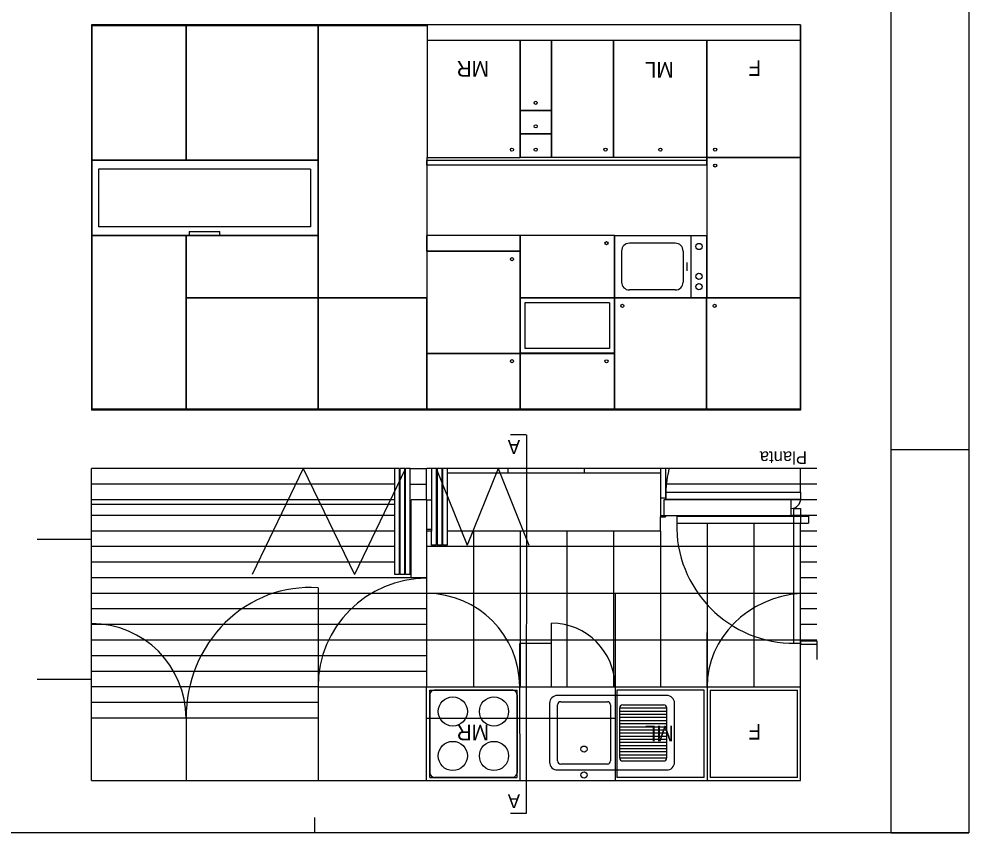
# Model space of a CAD drawing. Extents: x 1323.1 to 1334.7, y -308.5 to -300.1.
# Drawn here: x 1328.58 to 1334.67, y -308.54 to -303.32 of the extents above; entities that cross this region are included whole.
import ezdxf

# ---------------------------------------------------------------- set-up
doc = ezdxf.new("R2010")
doc.units = 0
for name, color, linetype in [('Level 1', 7, 'Continuous'), ('Level 10', 7, 'Continuous'), ('Level 11', 7, 'Continuous'), ('Level 13', 7, 'Continuous'), ('Level 2', 7, 'Continuous'), ('Level 3', 7, 'Continuous'), ('Level 31', 7, 'Continuous'), ('Level 37', 7, 'Continuous'), ('Level 4', 7, 'Continuous'), ('Level 59', 7, 'Continuous'), ('Level 60', 7, 'Continuous'), ('Level 62', 7, 'Continuous')]:
    doc.layers.add(name, color=color, linetype=linetype)

msp = doc.modelspace()

# ---------------------------------------------------------------- linework, layer by layer
at = {"layer": 'Level 1'}
for p, q in [((1333.5921, -303.3551), (1329.0421, -303.3551)), ((1329.0421, -303.3551), (1329.0421, -305.8251)), ((1333.5921, -303.3551), (1333.5921, -305.8251)), ((1333.5921, -305.8251), (1329.0421, -305.8251)), ((1329.0421, -306.6532), (1329.0421, -306.2007)), ((1331.1921, -306.4007), (1331.1921, -306.2007)), ((1331.2241, -306.2007), (1331.1935, -306.2007)), ((1331.2241, -306.2007), (1331.2241, -306.6007)), ((1332.6921, -306.2007), (1332.6921, -306.5107)), ((1332.7241, -306.2007), (1332.6921, -306.2007)), ((1332.7241, -306.2007), (1332.7241, -306.4007)), ((1331.0921, -306.9007), (1331.0921, -306.4007)), ((1331.1921, -306.4007), (1331.0921, -306.4007)), ((1331.1921, -306.4007), (1331.1921, -306.9007)), ((1331.1921, -306.4007), (1331.2241, -306.4007)), ((1332.7241, -306.3907), (1332.6921, -306.3907)), ((1332.6921, -306.4007), (1332.6921, -306.5007)), ((1333.5321, -306.4007), (1332.7141, -306.4007)), ((1332.7141, -306.4007), (1332.7141, -306.5007)), ((1333.5321, -306.5007), (1333.5321, -306.4007)), ((1333.5321, -306.5007), (1333.5321, -306.4007)), ((1332.6921, -306.5007), (1333.5321, -306.5007)), ((1332.6921, -306.5107), (1332.7241, -306.5107)), ((1332.7141, -306.5007), (1333.5321, -306.5007)), ((1332.7241, -306.5007), (1332.7241, -306.5107)), ((1331.2241, -306.5907), (1331.1921, -306.5907)), ((1328.6921, -306.6532), (1329.0421, -306.6532)), ((1331.2241, -306.6007), (1331.1921, -306.6007)), ((1331.1921, -306.9007), (1331.0921, -306.9007)), ((1333.5921, -307.3257), (1333.6971, -307.3257)), ((1333.5921, -308.2007), (1333.5921, -307.3257)), ((1333.5921, -308.2007), (1333.5921, -307.3257)), ((1333.6971, -307.3257), (1333.6971, -307.4257)), ((1329.0421, -307.5532), (1328.6921, -307.5532)), ((1329.0421, -308.2007), (1329.0421, -307.5507)), ((1329.0421, -308.2007), (1329.0421, -307.5532)), ((1329.0421, -308.2007), (1333.5921, -308.2007)), ((1329.0421, -308.2007), (1330.7921, -308.2007)), ((1330.8921, -308.2007), (1333.5921, -308.2007))]:
    msp.add_line(p, q, dxfattribs=at)
at = {"layer": 'Level 10'}
for p, q in [((1330.9871, -306.2007), (1329.0421, -306.2007)), ((1331.0871, -306.2007), (1331.1935, -306.2007)), ((1333.6971, -306.2007), (1332.7241, -306.2007)), ((1330.9871, -306.3007), (1329.0421, -306.3007)), ((1331.0871, -306.3007), (1331.1921, -306.3007)), ((1333.6971, -306.3007), (1332.7241, -306.3007)), ((1330.9871, -306.4007), (1329.0421, -306.4007)), ((1333.6971, -306.4007), (1333.5321, -306.4007)), ((1330.9871, -306.5007), (1329.0421, -306.5007)), ((1333.6971, -306.5007), (1333.5321, -306.5007)), ((1332.9921, -306.5507), (1332.9921, -307.6007)), ((1333.2921, -306.5507), (1333.2921, -307.6007)), ((1333.5921, -307.3057), (1333.5921, -306.5507)), ((1330.9871, -306.6007), (1329.0421, -306.6007)), ((1331.4921, -306.6007), (1331.4921, -307.5977)), ((1331.7921, -306.6007), (1331.7921, -307.6007)), ((1332.0921, -306.6007), (1332.0921, -307.6007)), ((1332.3921, -306.6007), (1332.3921, -307.6007)), ((1332.6921, -306.6007), (1332.6921, -307.6007)), ((1333.6971, -306.6007), (1333.5921, -306.6007)), ((1330.9871, -306.7007), (1329.0421, -306.7007)), ((1333.5921, -306.7007), (1331.1921, -306.7007)), ((1333.6971, -306.7007), (1333.5921, -306.7007)), ((1330.9871, -306.8007), (1329.0421, -306.8007)), ((1333.6971, -306.8007), (1333.5921, -306.8007)), ((1331.0921, -306.9007), (1329.0421, -306.9007)), ((1331.1921, -306.9007), (1331.1921, -307.5977)), ((1333.6971, -306.9007), (1333.5921, -306.9007)), ((1333.5921, -307.0007), (1329.0421, -307.0007)), ((1333.6971, -307.0007), (1333.5921, -307.0007)), ((1331.1921, -307.1007), (1329.0421, -307.1007)), ((1333.6971, -307.1007), (1333.5921, -307.1007)), ((1331.1921, -307.2007), (1329.0421, -307.2007)), ((1333.6971, -307.2007), (1333.5921, -307.2007)), ((1333.5921, -307.3007), (1329.0421, -307.3007)), ((1333.6971, -307.3007), (1333.5921, -307.3007)), ((1331.1921, -307.4007), (1329.0421, -307.4007)), ((1331.1921, -307.5007), (1329.0421, -307.5007)), ((1330.4951, -307.6007), (1329.0421, -307.6007)), ((1330.4951, -307.7007), (1329.0421, -307.7007))]:
    msp.add_line(p, q, dxfattribs=at)
at = {"layer": 'Level 11'}
for p, q in [((1331.7901, -304.7051), (1331.1941, -304.7051)), ((1331.1941, -304.8051), (1331.1941, -304.7051)), ((1331.7901, -304.7051), (1331.7901, -304.8051)), ((1332.3981, -304.7051), (1332.3981, -305.1051)), ((1332.3981, -304.7051), (1332.9881, -304.7051)), ((1332.8881, -304.7051), (1332.8881, -305.1051)), ((1332.9881, -304.7051), (1332.9881, -305.1051)), ((1332.7881, -304.7551), (1332.4931, -304.7551)), ((1331.7901, -304.8051), (1331.1941, -304.8051)), ((1332.4431, -304.8051), (1332.4431, -305.0051)), ((1332.8381, -304.8051), (1332.8381, -305.0051)), ((1332.8626, -304.8784), (1332.8626, -304.9318)), ((1332.7881, -305.0551), (1332.4931, -305.0551)), ((1332.9881, -305.1051), (1332.3981, -305.1051)), ((1331.7421, -307.6206), (1331.2421, -307.6206)), ((1333.0121, -307.6207), (1333.5721, -307.6207)), ((1333.0121, -307.6207), (1333.0121, -308.1807)), ((1333.5721, -308.1807), (1333.5721, -307.6207)), ((1331.2121, -307.6506), (1331.2121, -308.1506)), ((1331.7721, -307.6506), (1331.7721, -308.1506)), ((1332.0525, -307.6956), (1332.3525, -307.6956)), ((1332.0325, -308.0756), (1332.0325, -307.7156)), ((1332.3725, -307.7156), (1332.3725, -308.0756)), ((1332.431, -308.0556), (1332.431, -307.7356)), ((1332.431, -307.7356), (1332.7325, -307.7356)), ((1332.431, -307.7556), (1332.7325, -307.7556)), ((1332.4509, -307.7156), (1332.7125, -307.7156)), ((1332.7325, -308.0556), (1332.7325, -307.7356)), ((1332.431, -307.7756), (1332.7325, -307.7756)), ((1332.431, -307.7956), (1332.7325, -307.7956)), ((1332.431, -307.8156), (1332.7325, -307.8156)), ((1332.431, -307.8356), (1332.7325, -307.8356)), ((1332.431, -307.8556), (1332.7325, -307.8556)), ((1332.431, -307.8756), (1332.7325, -307.8756)), ((1332.431, -307.8956), (1332.7325, -307.8956)), ((1332.431, -307.9156), (1332.7325, -307.9156)), ((1332.431, -307.9356), (1332.7325, -307.9356)), ((1332.431, -307.9556), (1332.7325, -307.9556)), ((1332.431, -307.9756), (1332.7325, -307.9756)), ((1332.431, -307.9956), (1332.7325, -307.9956)), ((1332.431, -308.0156), (1332.7325, -308.0156)), ((1332.431, -308.0356), (1332.7325, -308.0356)), ((1332.431, -308.0556), (1332.7325, -308.0556)), ((1332.3525, -308.0956), (1332.0525, -308.0956)), ((1332.4509, -308.0756), (1332.7125, -308.0756)), ((1331.7421, -308.1806), (1331.2421, -308.1806)), ((1333.5721, -308.1807), (1333.0121, -308.1807))]:
    msp.add_line(p, q, dxfattribs=at)
for points in [[(1332.7328, -307.655), (1332.0314, -307.655)], [(1331.9814, -307.705), (1331.9814, -308.0834)], [(1332.7828, -308.0834), (1332.7828, -307.705)], [(1332.0314, -308.1334), (1332.7328, -308.1334)]]:
    msp.add_lwpolyline(points, dxfattribs=at)
for centre, radius in [((1332.9399, -304.7762), 0.02), ((1332.9399, -304.9668), 0.02), ((1332.9399, -305.0333), 0.02), ((1331.36, -307.758), 0.0936), ((1331.6242, -307.758), 0.0936), ((1331.36, -308.0432), 0.0936), ((1331.6242, -308.0432), 0.0936), ((1332.2025, -307.9996), 0.0199), ((1332.2025, -308.1655), 0.0199)]:
    msp.add_circle(centre, radius, dxfattribs=at)
for centre, radius, start, end in [((1332.4931, -304.8051), 0.05, 90, 180), ((1332.7881, -304.8051), 0.05, 0, 90), ((1332.4931, -305.0051), 0.05, 180, 270), ((1332.7881, -305.0051), 0.05, 270, 0), ((1331.2421, -307.6506), 0.03, 89.99998, 179.99995), ((1331.7421, -307.6506), 0.03, 359.9999, 89.99991), ((1332.0313, -307.705), 0.05, 90, 180), ((1332.0525, -307.7156), 0.02, 90, 180), ((1332.3525, -307.7156), 0.02, 0, 90), ((1332.7328, -307.705), 0.05, 0, 90), ((1332.4509, -307.7356), 0.02, 90, 180), ((1332.7125, -307.7356), 0.02, 0, 90), ((1332.4509, -308.0556), 0.02, 180, 270), ((1332.7125, -308.0556), 0.02, 270, 0), ((1332.0313, -308.0834), 0.05, 180, 270), ((1332.0525, -308.0756), 0.02, 180, 270), ((1332.3525, -308.0756), 0.02, 270, 0), ((1332.7328, -308.0834), 0.05, 270, 0), ((1331.2421, -308.1506), 0.03, 180.00001, 269.99979), ((1331.7421, -308.1506), 0.03, 269.9998, 0.00015)]:
    msp.add_arc(centre, radius, start, end, dxfattribs=at)
at = {"layer": 'Level 13'}
for p, q in [((1329.5141, -303.3601), (1329.0421, -303.3601)), ((1329.0441, -303.3601), (1329.0441, -304.2231)), ((1329.0441, -303.3601), (1329.0441, -304.7051)), ((1331.1921, -303.3601), (1329.5161, -303.3601)), ((1329.6461, -303.3601), (1329.6461, -304.2231)), ((1329.6481, -303.3601), (1329.6481, -304.2231)), ((1330.4941, -303.3551), (1330.4941, -304.2231)), ((1330.4961, -303.3551), (1330.4961, -305.1051)), ((1331.1948, -303.3551), (1331.1948, -304.2051)), ((1333.5901, -303.3551), (1333.5901, -305.1047)), ((1332.9941, -303.4551), (1331.1948, -303.4551)), ((1331.7898, -303.4551), (1331.1948, -303.4551)), ((1331.1948, -303.4551), (1331.1948, -304.2031)), ((1331.7901, -303.4551), (1331.7901, -304.2051)), ((1331.7921, -303.4551), (1331.7921, -303.9031)), ((1331.9921, -303.4551), (1331.9921, -303.9031)), ((1331.9941, -303.4551), (1331.9941, -304.2051)), ((1332.3901, -303.4551), (1332.3901, -304.2051)), ((1332.3921, -303.4551), (1332.3921, -304.2051)), ((1332.9881, -303.4551), (1332.9881, -304.2251)), ((1332.9901, -303.4551), (1332.9901, -305.1047)), ((1333.5901, -303.4551), (1332.9941, -303.4551)), ((1333.5901, -303.4551), (1333.5901, -305.8201)), ((1331.9921, -303.9031), (1331.7921, -303.9031)), ((1331.9921, -303.9051), (1331.7921, -303.9051)), ((1331.7921, -303.9051), (1331.7921, -304.0531)), ((1331.9921, -303.9051), (1331.9921, -304.0531)), ((1331.9921, -304.0531), (1331.7921, -304.0531)), ((1331.9921, -304.0551), (1331.7921, -304.0551)), ((1331.7921, -304.0551), (1331.7921, -304.2051)), ((1331.9921, -304.0551), (1331.9921, -304.2051)), ((1331.1941, -304.2051), (1331.7923, -304.2051)), ((1331.1941, -304.2051), (1331.1941, -305.8201)), ((1331.9921, -304.2051), (1331.7921, -304.2051)), ((1332.9881, -304.2051), (1331.9921, -304.2051)), ((1333.5901, -304.2051), (1332.9901, -304.2051)), ((1333.5901, -304.2071), (1332.9901, -304.2071)), ((1329.6461, -304.2231), (1329.0441, -304.2231)), ((1330.4941, -304.2251), (1329.0441, -304.2251)), ((1330.4459, -304.2801), (1329.0871, -304.2801)), ((1329.0871, -304.2801), (1329.0871, -304.6501)), ((1330.4941, -304.2231), (1329.6481, -304.2231)), ((1330.4459, -304.2801), (1330.4459, -304.6501)), ((1330.4941, -304.2251), (1330.4941, -304.7051)), ((1330.4941, -304.7051), (1329.0441, -304.7051)), ((1329.0441, -304.7071), (1329.0441, -305.8201)), ((1329.6461, -304.7071), (1329.0441, -304.7071)), ((1330.4459, -304.6501), (1329.0871, -304.6501)), ((1329.6461, -304.7071), (1329.6461, -305.8201)), ((1329.6481, -304.7051), (1329.8431, -304.7051)), ((1330.4941, -304.7071), (1329.6481, -304.7071)), ((1329.6481, -304.7071), (1329.6481, -305.1051)), ((1329.669, -304.6801), (1329.864, -304.6801)), ((1329.669, -304.6801), (1329.669, -304.7051)), ((1329.864, -304.7051), (1329.864, -304.6801)), ((1330.4941, -304.7071), (1330.4941, -305.1051)), ((1332.3981, -304.7051), (1331.7901, -304.7051)), ((1331.7921, -304.7051), (1331.7921, -305.1051)), ((1332.3961, -304.7051), (1332.3961, -305.1051)), ((1331.1941, -304.8071), (1331.7901, -304.8071)), ((1331.7901, -304.8071), (1331.7901, -305.4601)), ((1330.4941, -305.1051), (1329.6481, -305.1051)), ((1329.6481, -305.1071), (1329.6481, -305.8201)), ((1330.1401, -305.1071), (1329.6481, -305.1071)), ((1330.4941, -305.1071), (1330.1421, -305.1071)), ((1330.4941, -305.1071), (1330.4941, -305.8201)), ((1331.1941, -305.1051), (1330.4961, -305.1051)), ((1330.4961, -305.1071), (1330.4961, -305.8201)), ((1331.1921, -305.1071), (1330.4961, -305.1071)), ((1331.1921, -305.1051), (1331.1921, -305.8201)), ((1332.3961, -305.1051), (1331.7921, -305.1051)), ((1331.7921, -305.1071), (1331.7921, -305.4601)), ((1332.3961, -305.1071), (1331.7921, -305.1071)), ((1332.3961, -305.1071), (1332.3961, -305.4601)), ((1332.3981, -305.1071), (1332.3981, -305.8201)), ((1332.9881, -305.1071), (1332.3981, -305.1071)), ((1332.9881, -305.8201), (1332.9881, -305.1071)), ((1333.5901, -305.1047), (1332.9901, -305.1047)), ((1332.9901, -305.8201), (1332.9901, -305.1071)), ((1333.5901, -305.1071), (1332.9901, -305.1071)), ((1333.5901, -305.1071), (1333.5901, -305.8201)), ((1332.3661, -305.1367), (1331.8221, -305.1367)), ((1331.8221, -305.1367), (1331.8221, -305.4301)), ((1332.3661, -305.1367), (1332.3661, -305.4301)), ((1332.3661, -305.4301), (1331.8221, -305.4301)), ((1331.1941, -305.4601), (1331.7901, -305.4601)), ((1331.1941, -305.4621), (1331.7901, -305.4621)), ((1331.7901, -305.4621), (1331.7901, -305.8201)), ((1332.3961, -305.4601), (1331.7921, -305.4601)), ((1331.7921, -305.4621), (1331.7921, -305.8201)), ((1331.7921, -305.4621), (1332.3961, -305.4621)), ((1332.3961, -305.4621), (1332.3961, -305.8201)), ((1329.6461, -305.8201), (1329.0441, -305.8201)), ((1330.4941, -305.8201), (1329.6481, -305.8201)), ((1331.1921, -305.8201), (1330.4961, -305.8201)), ((1331.7901, -305.8201), (1331.1941, -305.8201)), ((1332.3961, -305.8201), (1331.7921, -305.8201)), ((1333.1426, -305.8201), (1332.3981, -305.8201)), ((1333.5901, -305.8201), (1333.1446, -305.8201)), ((1330.9871, -306.8807), (1330.9871, -306.2007)), ((1331.0171, -306.2007), (1330.9871, -306.2007)), ((1331.0171, -306.2007), (1330.9871, -306.2007)), ((1331.0171, -306.8807), (1331.0171, -306.2007)), ((1331.0221, -306.8807), (1331.0221, -306.2007)), ((1331.0521, -306.2007), (1331.0221, -306.2007)), ((1331.0521, -306.2007), (1331.0221, -306.2007)), ((1331.0521, -306.8807), (1331.0521, -306.2007)), ((1331.0571, -306.8807), (1331.0571, -306.2007)), ((1331.0871, -306.2007), (1331.0571, -306.2007)), ((1331.0871, -306.2007), (1331.0571, -306.2007)), ((1331.0871, -306.8807), (1331.0871, -306.2007)), ((1332.6921, -306.2007), (1331.2241, -306.2007)), ((1331.2541, -306.2007), (1331.2541, -306.6907)), ((1331.2591, -306.2007), (1331.2591, -306.6907)), ((1331.2891, -306.2007), (1331.2891, -306.6907)), ((1331.2941, -306.2007), (1331.2941, -306.6907)), ((1331.3241, -306.2007), (1331.3241, -306.6907)), ((1332.7263, -306.3507), (1333.5921, -306.3507)), ((1332.7263, -306.3507), (1332.7263, -306.3957)), ((1333.5921, -306.3507), (1333.5921, -306.3957)), ((1332.7263, -306.3957), (1333.5921, -306.3957)), ((1332.7971, -306.5057), (1333.6421, -306.5057)), ((1332.7971, -306.5057), (1332.7971, -306.5507)), ((1333.6421, -306.5057), (1333.6421, -306.5507)), ((1332.7971, -306.5507), (1333.6421, -306.5507)), ((1331.2241, -306.6907), (1331.2241, -306.6007)), ((1331.2541, -306.6907), (1331.2241, -306.6907)), ((1331.2891, -306.6907), (1331.2591, -306.6907)), ((1331.3241, -306.6907), (1331.2941, -306.6907)), ((1331.0171, -306.8807), (1330.9871, -306.8807)), ((1331.0521, -306.8807), (1331.0221, -306.8807)), ((1331.0871, -306.8807), (1331.0571, -306.8807)), ((1330.4951, -307.6007), (1333.5921, -307.6007)), ((1330.4951, -307.6007), (1330.4951, -308.2007)), ((1332.9921, -307.6007), (1332.9921, -308.2007)), ((1330.4951, -307.8007), (1329.0421, -307.8007))]:
    msp.add_line(p, q, dxfattribs=at)
for centre in [(1331.8921, -303.8551), (1331.8921, -304.0051), (1331.7399, -304.1551), (1331.8921, -304.1551), (1332.3401, -304.1551), (1332.6921, -304.1551), (1333.0441, -304.1551), (1333.0441, -304.2571), (1332.3461, -304.7551), (1331.7401, -304.8571), (1332.4481, -305.1567), (1333.0401, -305.1567), (1331.7401, -305.5117), (1332.3461, -305.5121)]:
    msp.add_circle(centre, 0.01, dxfattribs=at)
at = {"layer": 'Level 2'}
for p, q in [((1332.6921, -306.6007), (1332.6921, -306.5107)), ((1329.0421, -307.5532), (1329.0421, -306.6532)), ((1329.0421, -307.5532), (1329.0421, -306.6532)), ((1331.2591, -306.6007), (1331.2541, -306.6007)), ((1331.2941, -306.6007), (1331.2891, -306.6007)), ((1332.6921, -306.6007), (1331.3241, -306.6007))]:
    msp.add_line(p, q, dxfattribs=at)
at = {"layer": 'Level 3'}
for p, q in [((1331.1921, -307.8007), (1331.1921, -307.6007)), ((1332.4021, -307.6007), (1332.4021, -308.2007)), ((1331.1921, -307.8007), (1332.4021, -307.8007))]:
    msp.add_line(p, q, dxfattribs=at)
at = {"layer": 'Level 31'}
for p, q in [((1333.5921, -307.3057), (1333.6971, -307.3057)), ((1333.5921, -307.3057), (1333.5921, -307.3257)), ((1333.6971, -307.3057), (1333.6971, -307.3257))]:
    msp.add_line(p, q, dxfattribs=at)
at = {"layer": 'Level 37'}
for p, q in [((1332.9881, -304.2251), (1331.1941, -304.2251)), ((1331.1941, -304.2551), (1331.1941, -304.2251)), ((1332.9881, -304.2551), (1331.1941, -304.2551)), ((1332.9881, -304.2251), (1332.9881, -304.2551))]:
    msp.add_line(p, q, dxfattribs=at)
at = {"layer": 'Level 4'}
for p, q in [((1330.4004, -306.2007), (1330.072, -306.8807)), ((1330.4004, -306.2007), (1330.7287, -306.8807)), ((1331.0571, -306.2007), (1330.7287, -306.8807)), ((1331.2541, -306.2007), (1331.4523, -306.6907)), ((1331.2591, -306.2307), (1331.2541, -306.2307)), ((1331.2941, -306.2307), (1331.2891, -306.2307)), ((1332.6921, -306.2307), (1331.3241, -306.2307)), ((1331.6506, -306.2007), (1331.4523, -306.6907)), ((1331.6506, -306.2007), (1331.8488, -306.6907)), ((1331.7134, -306.2007), (1331.7134, -306.2307)), ((1332.2028, -306.2007), (1332.2028, -306.2307)), ((1333.5921, -306.3507), (1333.5921, -306.2007)), ((1330.9871, -306.4307), (1329.0421, -306.4307)), ((1333.5471, -306.4557), (1333.5471, -307.3207)), ((1333.5471, -306.4557), (1333.5921, -306.4557)), ((1333.5921, -306.4557), (1333.5921, -306.5507)), ((1330.4951, -306.9656), (1330.4951, -307.8007)), ((1332.4021, -307.0007), (1332.4021, -307.6007)), ((1332.9921, -307.0007), (1332.4021, -307.0007)), ((1333.5921, -307.6007), (1333.5921, -307.0007)), ((1331.9941, -307.6007), (1331.9941, -307.1927)), ((1332.9921, -307.6007), (1332.9921, -307.2507)), ((1331.9941, -307.3232), (1331.7898, -307.3232)), ((1331.7898, -307.6007), (1331.7898, -307.3232)), ((1333.5571, -307.3207), (1333.5921, -307.3207)), ((1331.2121, -307.6207), (1331.7721, -307.6207)), ((1331.2121, -308.1807), (1331.2121, -307.6207)), ((1331.7721, -308.1807), (1331.7721, -307.6207)), ((1331.7921, -308.2007), (1331.7898, -307.6007)), ((1332.9721, -307.6207), (1332.4121, -307.6207)), ((1332.4121, -307.6207), (1332.4121, -308.1807)), ((1332.9721, -308.1807), (1332.9721, -307.6207)), ((1333.5921, -308.2007), (1333.5921, -307.6007)), ((1329.6481, -307.8007), (1329.6481, -308.2007)), ((1331.1921, -308.2007), (1331.1921, -307.8007)), ((1331.2121, -308.1807), (1331.7721, -308.1807)), ((1332.9721, -308.1807), (1332.4121, -308.1807))]:
    msp.add_line(p, q, dxfattribs=at)
for centre, radius, start, end in [((1333.5321, -306.3957), 0.06, 269.99697, 0.00144), ((1333.5509, -306.5664), 0.7542, 178.80149, 270.47032), ((1331.1921, -307.6007), 0.697, 90, 180), ((1331.1898, -307.6007), 0.6, 0, 89.7775), ((1329.0421, -307.8007), 0.606, 0, 90), ((1331.9941, -307.6007), 0.408, 0, 90)]:
    msp.add_arc(centre, radius, start, end, dxfattribs=at)
for centre, major_axis, ratio, start_param, end_param in [((1333.5241, -306.4186), (0, -0.9179), 0.871521, 4.472668, 4.638298), ((1330.4384, -307.8007), (0, -0.8372), 0.943954, 3.069792, 4.712389), ((1333.6429, -307.6007), (-0.6509, 0), 0.924693, 4.790593, 6.283185)]:
    msp.add_ellipse(centre, major_axis=major_axis, ratio=ratio, start_param=start_param, end_param=end_param, dxfattribs=at)
at = {"layer": 'Level 59'}
for p, q in [((1331.8307, -305.9833), (1331.7309, -305.9833)), ((1331.8323, -305.9833), (1331.8307, -308.4121)), ((1331.8307, -308.4121), (1331.7309, -308.4121))]:
    msp.add_line(p, q, dxfattribs=at)
at = {"layer": 'Level 62'}
for p, q in [((1334.1727, -308.5374), (1334.1727, -300.1374)), ((1334.1727, -306.0774), (1334.6727, -306.0774)), ((1330.4723, -308.4374), (1330.4723, -308.5374)), ((1334.1727, -308.5374), (1334.6727, -308.5374))]:
    msp.add_line(p, q, dxfattribs=at)
msp.add_lwpolyline([(1334.6727, -300.1374), (1334.6727, -308.5374), (1323.0731, -308.5374), (1323.0731, -300.1374)], close=True, dxfattribs=at)

# ---------------------------------------------------------------- texts
at = {"layer": 'Level 11'}
for s, p in [('MR', (1331.5922, -303.5869)), ('ML', (1332.778, -303.5935)), ('F', (1333.339, -303.5818)), ('MR', (1331.5922, -307.8429)), ('ML', (1332.778, -307.8495)), ('F', (1333.339, -307.8379))]:
    msp.add_text(s, height=0.1, rotation=180, dxfattribs=at).set_placement(p)
at = {"layer": 'Level 59'}
for rotation, p in [(180.00018, (1331.7916, -306.0179)), (179.99982, (1331.7916, -308.2896))]:
    msp.add_text('A', height=0.088, rotation=rotation, dxfattribs=at).set_placement(p)
at = {"layer": 'Level 60'}
msp.add_text('Planta', height=0.08, rotation=180.00001, dxfattribs=at).set_placement((1333.6333, -306.0903))

doc.saveas('drawing.dxf')
